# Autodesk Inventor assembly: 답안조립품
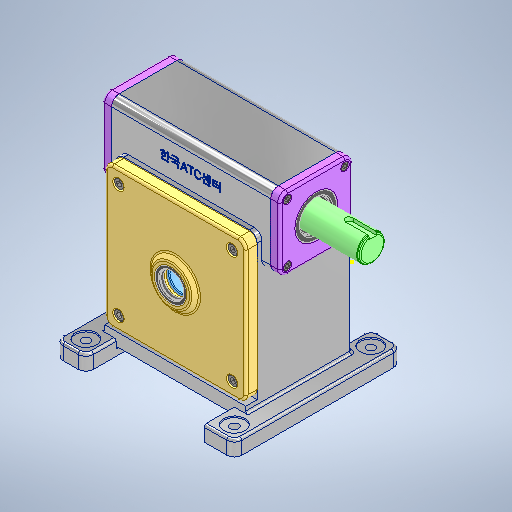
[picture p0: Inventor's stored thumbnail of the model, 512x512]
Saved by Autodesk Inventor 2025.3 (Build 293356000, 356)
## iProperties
Created: 2025-06
Part Number: 답안조립품
Document SubType Name: Assembly
Designer: PC-10
Author: PC-10
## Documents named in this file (13)
- C:\Users\PC-10\Desktop\새 폴더\답안조립품.iam
- C:\Users\PC-10\Desktop\새 폴더\750603V1015\웜 휠\웜 휠.ipt
- C:\Users\PC-10\Desktop\새 폴더\750603V1015\6각 구멍붙이 볼트 M6x12\6각 구멍붙이 볼트 M6x12.ipt
- C:\Users\PC-10\Desktop\새 폴더\750603V1015\6각 구멍붙이 볼트 M8x20\6각 구멍붙이 볼트 M8x20.ipt
- C:\Users\PC-10\Desktop\새 폴더\750603V1015\깊은 홈 볼 베어링 6206\깊은 홈 볼 베어링 6206.ipt
- C:\Users\PC-10\Desktop\새 폴더\750603V1015\깊은 홈 볼 베어링 6209\깊은 홈 볼 베어링 6209.ipt
- C:\Users\PC-10\Desktop\새 폴더\750603V1015\뒷커버\뒷커버.ipt
- C:\Users\PC-10\Desktop\새 폴더\750603V1015\본체.ipt
- C:\Users\PC-10\Desktop\새 폴더\750603V1015\앞커버\앞커버.ipt
- C:\Users\PC-10\Desktop\새 폴더\750603V1015\오일 실 30 42 7\오일 실 30 42 7.ipt
- C:\Users\PC-10\Desktop\새 폴더\750603V1015\오일 실 35 55 11\오일 실 35 55 11.ipt
- C:\Users\PC-10\Desktop\새 폴더\750603V1015\웜 샤프트\웜 샤프트.ipt
- C:\Users\PC-10\Desktop\새 폴더\750603V1015\웜 휠 커버\웜 휠 커버.ipt
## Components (12 placed, 2 different names)
1. 6각 구멍붙이 볼트 M6x12:1
2. 6각 구멍붙이 볼트 M6x12:2
3. 6각 구멍붙이 볼트 M6x12:3
4. 6각 구멍붙이 볼트 M6x12:4
5. 6각 구멍붙이 볼트 M6x12:5
6. 6각 구멍붙이 볼트 M6x12:6
7. 6각 구멍붙이 볼트 M6x12:7
8. 6각 구멍붙이 볼트 M6x12:8
9. 6각 구멍붙이 볼트 M8x20:2
10. 6각 구멍붙이 볼트 M8x20:3
11. 6각 구멍붙이 볼트 M8x20:4
12. 6각 구멍붙이 볼트 M8x20:5
